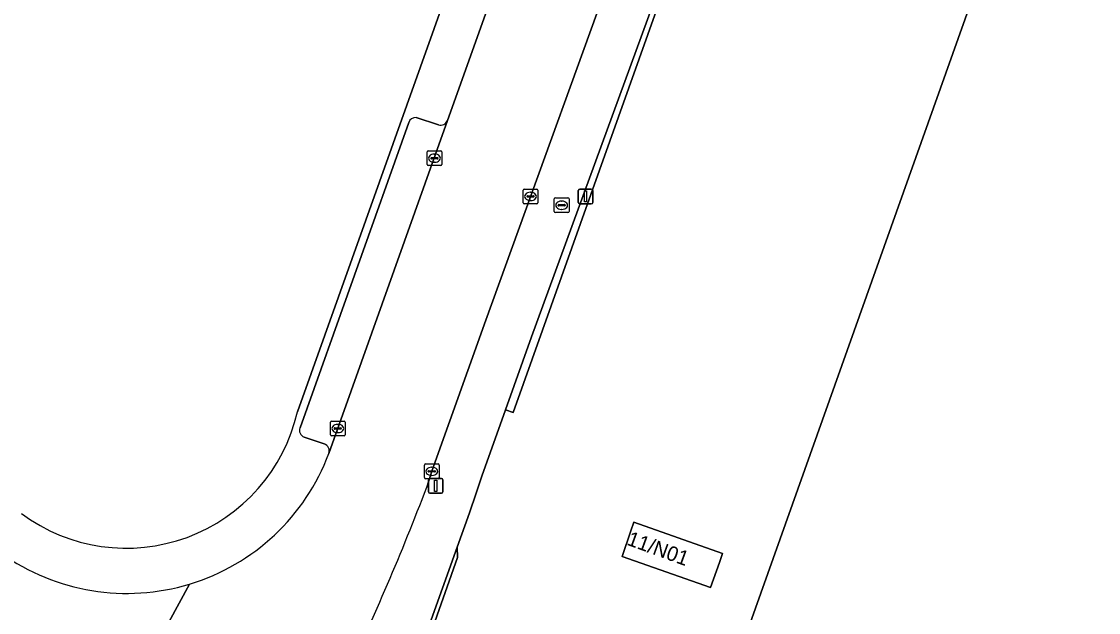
# Model space of a CAD drawing. Extents: x 155018 to 156648, y 383979 to 385733.
# Drawn here: x 155651.5 to 155724.8, y 384875.8 to 384916 of the extents above; entities that cross this region are included whole.
import ezdxf

# ---------------------------------------------------------------- set-up
doc = ezdxf.new("R2010")
doc.units = 0
for name, color, linetype in [('IMGEO_Brandkraan', 7, 'Continuous'), ('IMGEO_Erf', 7, 'Continuous'), ('IMGEO_Groenvoorziening', 7, 'Continuous'), ('IMGEO_Hek', 7, 'Continuous'), ('IMGEO_Kolk', 7, 'Continuous'), ('IMGEO_Lichtmast', 7, 'Continuous'), ('IMGEO_Pand', 7, 'Continuous'), ('IMGEO_Pand_nummerreeks', 7, 'Continuous'), ('IMGEO_Parkeervlak_open', 7, 'Continuous'), ('IMGEO_Rijbaan_lokaal_gesloten', 7, 'Continuous'), ('IMGEO_Voetpad_open', 7, 'Continuous')]:
    doc.layers.add(name, color=color, linetype=linetype)

msp = doc.modelspace()

# ---------------------------------------------------------------- linework, layer by layer
at = {"layer": 'IMGEO_Brandkraan'}
for p, q in [((155687.748, 384903.067), (155687.748, 384903.919)), ((155687.823, 384903.993), (155688.675, 384903.993)), ((155688.007, 384903.487), (155688.007, 384903.499)), ((155688.445, 384903.45), (155688.047, 384903.45)), ((155688.05, 384903.536), (155688.448, 384903.536)), ((155688.236, 384903.773), (155688.261, 384903.773)), ((155688.491, 384903.499), (155688.491, 384903.487)), ((155688.749, 384903.919), (155688.749, 384903.067)), ((155688.675, 384902.993), (155687.823, 384902.993)), ((155688.259, 384903.213), (155688.234, 384903.213))]:
    msp.add_line(p, q, dxfattribs=at)
for points in [[(155687.748, 384903.067), (155687.748, 384903.919)], [(155687.823, 384903.993), (155688.675, 384903.993)], [(155688.749, 384903.919), (155688.749, 384903.067)], [(155688.675, 384902.993), (155687.823, 384902.993)]]:
    msp.add_lwpolyline(points, dxfattribs=at)
for centre, radius, start, end in [((155687.825, 384903.917), 0.0765, 91.55205, 178.44795), ((155687.825, 384903.917), 0.0765, 91.55205, 178.44795), ((155688.047, 384903.496), 0.0403, 85.87752, 175.75265), ((155688.044, 384903.486), 0.0366, 178.93798, 274.71019), ((155688.448, 384903.493), 0.043, 264.86636, 352.45326), ((155688.452, 384903.498), 0.0386, 1.73085, 96.63898), ((155688.673, 384903.917), 0.0765, 1.55205, 88.44795), ((155688.673, 384903.917), 0.0765, 1.55205, 88.44795), ((155687.825, 384903.069), 0.0765, 181.55205, 268.44795), ((155687.825, 384903.069), 0.0765, 181.55205, 268.44795), ((155688.673, 384903.069), 0.0765, 271.55205, 358.44795), ((155688.673, 384903.069), 0.0765, 271.55205, 358.44795)]:
    msp.add_arc(centre, radius, start, end, dxfattribs=at)
for centre, major_axis, ratio, start_param, end_param in [((155688.235, 384903.493), (-0.387, 0.002), 0.722429, 4.712389, 7.853982), ((155688.26, 384903.493), (-0.39, 0.002), 0.717154, 1.570796, 4.712389)]:
    msp.add_ellipse(centre, major_axis=major_axis, ratio=ratio, start_param=start_param, end_param=end_param, dxfattribs=at)
at = {"layer": 'IMGEO_Erf'}
for points in [[(155819.22, 384821.585), (155773.299, 384837.894), (155771.729, 384833.45), (155765.854, 384835.53), (155767.438, 384839.985), (155767.038, 384840.129), (155766.348, 384838.189), (155696.765, 384862.93), (155727.468, 384949.235), (155728.915, 384948.717), (155740.174, 384980.395), (155746.303, 384997.642), (155748.837, 385004.772), (155747.33, 385005.279), (155749.138, 385010.33), (155750.623, 385009.797), (155753.183, 385017.001), (155762.359, 385042.817)], [(155730.975, 385018.536), (155724.402, 385000), (155719.139, 384985.171), (155718.598, 384983.687), (155716.009, 384976.585), (155715.7, 384975.738), (155702.844, 384939.771), (155702.172, 384937.868), (155696.786, 384922.628), (155696.12, 384920.743), (155684.958, 384889.381), (155684.425, 384889.57), (155682.806, 384885.06), (155682.424, 384883.902), (155681.972, 384882.563), (155681.138, 384880.234), (155681.15, 384879.519), (155676.547, 384866.454), (155676.35, 384866.575), (155669.497, 384856.797), (155669.212, 384856.331), (155667.198, 384853.508), (155667.02, 384853.625), (155588.106, 384741.158)], [(155670.262, 384889.44), (155694.342, 384956.978)]]:
    msp.add_lwpolyline(points, dxfattribs=at)
msp.add_lwpolyline([(155698.983, 384879.192), (155698.375, 384877.482), (155692.358, 384879.59), (155692.96, 384881.34), (155693.162, 384881.929), (155699.197, 384879.795)], close=True, dxfattribs=at)
msp.add_arc((155658.606, 384892.113), 11.959, 233.42553, 347.08496, dxfattribs=at)
at = {"layer": 'IMGEO_Groenvoorziening'}
for points in [[(155684.958, 384889.381), (155696.12, 384920.743), (155696.786, 384922.628), (155696.507, 384922.737), (155686.206, 384894.532), (155684.425, 384889.57)], [(155681.15, 384879.519), (155681.138, 384880.234), (155676.369, 384866.915), (155676.09, 384867.098), (155676.052, 384866.993), (155676.35, 384866.575), (155676.547, 384866.454)]]:
    msp.add_lwpolyline(points, close=True, dxfattribs=at)
at = {"layer": 'IMGEO_Hek'}
for points in [[(155696.786, 384922.628), (155696.12, 384920.743), (155684.958, 384889.381)], [(155681.15, 384879.519), (155676.547, 384866.454), (155676.35, 384866.575)]]:
    msp.add_lwpolyline(points, dxfattribs=at)
at = {"layer": 'IMGEO_Kolk'}
for p, q in [((155679.088, 384906.271), (155679.088, 384907.123)), ((155679.163, 384907.197), (155680.015, 384907.197)), ((155679.576, 384906.977), (155679.601, 384906.977)), ((155680.089, 384907.123), (155680.089, 384906.271)), ((155679.347, 384906.691), (155679.347, 384906.703)), ((155679.785, 384906.654), (155679.387, 384906.654)), ((155679.39, 384906.74), (155679.788, 384906.74)), ((155679.599, 384906.417), (155679.574, 384906.417)), ((155679.831, 384906.703), (155679.831, 384906.691)), ((155680.015, 384906.197), (155679.163, 384906.197)), ((155685.628, 384903.668), (155685.628, 384904.52)), ((155685.703, 384904.594), (155686.555, 384904.594)), ((155685.887, 384904.088), (155685.887, 384904.1)), ((155686.325, 384904.051), (155685.927, 384904.051)), ((155685.93, 384904.137), (155686.328, 384904.137)), ((155686.116, 384904.374), (155686.141, 384904.374)), ((155686.371, 384904.1), (155686.371, 384904.088)), ((155686.629, 384904.52), (155686.629, 384903.668)), ((155686.555, 384903.594), (155685.703, 384903.594)), ((155686.139, 384903.814), (155686.114, 384903.814)), ((155672.509, 384887.876), (155672.509, 384888.728)), ((155672.584, 384888.802), (155673.436, 384888.802)), ((155673.51, 384888.728), (155673.51, 384887.876)), ((155672.768, 384888.296), (155672.768, 384888.308)), ((155673.206, 384888.259), (155672.808, 384888.259)), ((155672.811, 384888.345), (155673.209, 384888.345)), ((155673.02, 384888.022), (155672.995, 384888.022)), ((155672.997, 384888.582), (155673.022, 384888.582)), ((155673.252, 384888.308), (155673.252, 384888.296)), ((155673.436, 384887.802), (155672.584, 384887.802)), ((155678.907, 384884.96), (155678.907, 384885.812)), ((155678.982, 384885.886), (155679.834, 384885.886)), ((155679.908, 384885.812), (155679.908, 384884.96)), ((155679.166, 384885.38), (155679.166, 384885.392)), ((155679.604, 384885.343), (155679.206, 384885.343)), ((155679.209, 384885.429), (155679.607, 384885.429)), ((155679.418, 384885.106), (155679.393, 384885.106)), ((155679.395, 384885.666), (155679.42, 384885.666)), ((155679.65, 384885.392), (155679.65, 384885.38)), ((155679.834, 384884.886), (155678.982, 384884.886))]:
    msp.add_line(p, q, dxfattribs=at)
for points in [[(155679.088, 384906.271), (155679.088, 384907.123)], [(155679.163, 384907.197), (155680.015, 384907.197)], [(155680.089, 384907.123), (155680.089, 384906.271)], [(155680.015, 384906.197), (155679.163, 384906.197)], [(155685.628, 384903.668), (155685.628, 384904.52)], [(155685.703, 384904.594), (155686.555, 384904.594)], [(155686.629, 384904.52), (155686.629, 384903.668)], [(155686.555, 384903.594), (155685.703, 384903.594)], [(155672.509, 384887.876), (155672.509, 384888.728)], [(155672.584, 384888.802), (155673.436, 384888.802)], [(155673.51, 384888.728), (155673.51, 384887.876)], [(155673.436, 384887.802), (155672.584, 384887.802)], [(155678.907, 384884.96), (155678.907, 384885.812)], [(155678.982, 384885.886), (155679.834, 384885.886)], [(155679.908, 384885.812), (155679.908, 384884.96)], [(155679.834, 384884.886), (155678.982, 384884.886)]]:
    msp.add_lwpolyline(points, dxfattribs=at)
for centre, radius, start, end in [((155679.165, 384907.121), 0.0765, 91.55205, 178.44795), ((155679.165, 384907.121), 0.0765, 91.55205, 178.44795), ((155680.013, 384907.121), 0.0765, 1.55205, 88.44795), ((155680.013, 384907.121), 0.0765, 1.55205, 88.44795), ((155679.165, 384906.273), 0.0765, 181.55205, 268.44795), ((155679.165, 384906.273), 0.0765, 181.55205, 268.44795), ((155679.387, 384906.7), 0.0403, 85.87752, 175.75265), ((155679.384, 384906.69), 0.0366, 178.93798, 274.71019), ((155679.788, 384906.697), 0.043, 264.86636, 352.45326), ((155679.792, 384906.702), 0.0386, 1.73085, 96.63898), ((155680.013, 384906.273), 0.0765, 271.55205, 358.44795), ((155680.013, 384906.273), 0.0765, 271.55205, 358.44795), ((155685.705, 384904.518), 0.0765, 91.55205, 178.44795), ((155685.705, 384904.518), 0.0765, 91.55205, 178.44795), ((155685.927, 384904.097), 0.0403, 85.87752, 175.75265), ((155685.924, 384904.087), 0.0366, 178.93798, 274.71019), ((155686.328, 384904.094), 0.043, 264.86636, 352.45326), ((155686.332, 384904.099), 0.0386, 1.73085, 96.63898), ((155686.553, 384904.518), 0.0765, 1.55205, 88.44795), ((155686.553, 384904.518), 0.0765, 1.55205, 88.44795), ((155685.705, 384903.67), 0.0765, 181.55205, 268.44795), ((155685.705, 384903.67), 0.0765, 181.55205, 268.44795), ((155686.553, 384903.67), 0.0765, 271.55205, 358.44795), ((155686.553, 384903.67), 0.0765, 271.55205, 358.44795), ((155672.586, 384888.726), 0.0765, 91.55205, 178.44795), ((155672.586, 384888.726), 0.0765, 91.55205, 178.44795), ((155673.434, 384888.726), 0.0765, 1.55205, 88.44795), ((155673.434, 384888.726), 0.0765, 1.55205, 88.44795), ((155672.808, 384888.305), 0.0403, 85.87752, 175.75265), ((155672.805, 384888.295), 0.0366, 178.93798, 274.71019), ((155673.209, 384888.302), 0.043, 264.86636, 352.45326), ((155673.213, 384888.307), 0.0386, 1.73085, 96.63898), ((155672.586, 384887.878), 0.0765, 181.55205, 268.44795), ((155672.586, 384887.878), 0.0765, 181.55205, 268.44795), ((155673.434, 384887.878), 0.0765, 271.55205, 358.44795), ((155673.434, 384887.878), 0.0765, 271.55205, 358.44795), ((155678.984, 384885.81), 0.0765, 91.55205, 178.44795), ((155678.984, 384885.81), 0.0765, 91.55205, 178.44795), ((155679.832, 384885.81), 0.0765, 1.55205, 88.44795), ((155679.832, 384885.81), 0.0765, 1.55205, 88.44795), ((155678.984, 384884.962), 0.0765, 181.55205, 268.44795), ((155678.984, 384884.962), 0.0765, 181.55205, 268.44795), ((155679.206, 384885.389), 0.0403, 85.87752, 175.75265), ((155679.203, 384885.379), 0.0366, 178.93798, 274.71019), ((155679.607, 384885.386), 0.043, 264.86636, 352.45326), ((155679.611, 384885.391), 0.0386, 1.73085, 96.63898), ((155679.832, 384884.962), 0.0765, 271.55205, 358.44795), ((155679.832, 384884.962), 0.0765, 271.55205, 358.44795)]:
    msp.add_arc(centre, radius, start, end, dxfattribs=at)
for centre, major_axis, ratio, start_param, end_param in [((155679.575, 384906.697), (-0.387, 0.002), 0.722429, 4.712389, 7.853982), ((155679.6, 384906.697), (-0.39, 0.002), 0.717154, 1.570796, 4.712389), ((155686.115, 384904.094), (-0.387, 0.002), 0.722429, 4.712389, 7.853982), ((155686.14, 384904.094), (-0.39, 0.002), 0.717154, 1.570796, 4.712389), ((155672.996, 384888.302), (-0.387, 0.002), 0.722429, 4.712389, 7.853982), ((155673.021, 384888.302), (-0.39, 0.002), 0.717154, 1.570796, 4.712389), ((155679.394, 384885.386), (-0.387, 0.002), 0.722429, 4.712389, 7.853982), ((155679.419, 384885.386), (-0.39, 0.002), 0.717154, 1.570796, 4.712389)]:
    msp.add_ellipse(centre, major_axis=major_axis, ratio=ratio, start_param=start_param, end_param=end_param, dxfattribs=at)
at = {"layer": 'IMGEO_Lichtmast'}
for p, q in [((155689.378, 384903.69), (155689.378, 384904.49)), ((155689.378, 384904.49), (155689.378, 384903.69)), ((155689.478, 384904.59), (155690.268, 384904.59)), ((155690.268, 384904.59), (155689.478, 384904.59)), ((155690.368, 384904.49), (155690.368, 384903.69)), ((155690.368, 384903.69), (155690.368, 384904.49)), ((155690.268, 384903.59), (155689.478, 384903.59)), ((155689.478, 384903.59), (155690.268, 384903.59)), ((155679.173, 384883.998), (155679.173, 384884.798)), ((155679.173, 384884.798), (155679.173, 384883.998)), ((155679.273, 384884.898), (155680.063, 384884.898)), ((155680.063, 384884.898), (155679.273, 384884.898)), ((155680.163, 384884.798), (155680.163, 384883.998)), ((155680.163, 384883.998), (155680.163, 384884.798)), ((155680.063, 384883.898), (155679.273, 384883.898)), ((155679.273, 384883.898), (155680.063, 384883.898))]:
    msp.add_line(p, q, dxfattribs=at)
for points in [[(155689.798, 384904.465), (155689.948, 384904.465), (155689.948, 384903.715), (155689.798, 384903.715), (155689.798, 384904.465)], [(155679.593, 384884.773), (155679.743, 384884.773), (155679.743, 384884.023), (155679.593, 384884.023), (155679.593, 384884.773)]]:
    msp.add_lwpolyline(points, dxfattribs=at)
for centre, start, end in [((155689.478, 384904.49), 90, 180), ((155689.478, 384904.49), 90, 180), ((155690.268, 384904.49), 0, 90), ((155690.268, 384904.49), 360, 90), ((155689.478, 384903.69), 180, 270), ((155689.478, 384903.69), 180, 270), ((155690.268, 384903.69), 270, 0), ((155690.268, 384903.69), 270, 0), ((155679.273, 384884.798), 90, 180), ((155679.273, 384884.798), 90, 180), ((155680.063, 384884.798), 0, 90), ((155680.063, 384884.798), 360, 90), ((155679.273, 384883.998), 180, 270), ((155679.273, 384883.998), 180, 270), ((155680.063, 384883.998), 270, 0), ((155680.063, 384883.998), 270, 0)]:
    msp.add_arc(centre, 0.1, start, end, dxfattribs=at)
at = {"layer": 'IMGEO_Pand'}
msp.add_lwpolyline([(155828.255, 384911.336), (155796.179, 384922.734), (155808.139, 384956.274), (155787.494, 384963.57), (155797.027, 384990.446), (155809.649, 385026.028), (155762.359, 385042.817), (155753.183, 385017.001), (155750.623, 385009.797), (155749.138, 385010.33), (155747.33, 385005.279), (155748.837, 385004.772), (155746.303, 384997.642), (155740.174, 384980.395), (155728.915, 384948.717), (155727.468, 384949.235), (155696.765, 384862.93), (155766.348, 384838.189), (155767.038, 384840.129), (155767.438, 384839.985), (155765.854, 384835.53), (155771.729, 384833.45), (155773.299, 384837.894), (155819.22, 384821.585)], dxfattribs=at)
msp.add_lwpolyline([(155698.983, 384879.192), (155699.197, 384879.795), (155693.162, 384881.929), (155692.96, 384881.34), (155692.358, 384879.59), (155698.375, 384877.482)], close=True, dxfattribs=at)
at = {"layer": 'IMGEO_Parkeervlak_open'}
for points in [[(155672.406, 384886.601), (155680.471, 384909.27)], [(155679.86, 384908.959), (155678.342, 384909.455)], [(155677.837, 384909.136), (155670.437, 384888.352)], [(155670.727, 384887.719), (155672.089, 384887.255)]]:
    msp.add_lwpolyline(points, dxfattribs=at)
for centre, radius, start, end in [((155678.292, 384908.975), 0.482, 84.0123, 160.54753), ((155679.997, 384909.446), 0.506, 254.29188, 339.66045), ((155670.876, 384888.17), 0.475, 157.46603, 251.7624), ((155671.903, 384886.761), 0.528, 342.37794, 69.34187)]:
    msp.add_arc(centre, radius, start, end, dxfattribs=at)
at = {"layer": 'IMGEO_Rijbaan_lokaal_gesloten'}
for points in [[(155764.837, 385117.429), (155755.507, 385119.738), (155752.407, 385110.986), (155749.126, 385101.756), (155741.863, 385081.49), (155734.635, 385061.204), (155727.42, 385041.095), (155724.606, 385033.163), (155719.998, 385020.177), (155712.839, 385000), (155711.66, 384996.694), (155697.277, 384956.434), (155683.176, 384916.819), (155680.471, 384909.27), (155672.406, 384886.601)], [(155679.062, 384884.306), (155679.409, 384885.386), (155683.078, 384895.663), (155693.322, 384923.959), (155698.719, 384939.029), (155712.551, 384977.822), (155712.738, 384978.347), (155715.089, 384984.941), (155720.459, 385000), (155723.632, 385008.98), (155724.976, 385012.761), (155727.017, 385018.428), (155728.003, 385021.255), (155731.055, 385029.838), (155733.848, 385037.615), (155741.439, 385058.768), (155756.537, 385101.063), (155759.644, 385109.754)], [(155654.873, 384862.94), (155662.924, 384877.712)], [(155662.924, 384877.712), (155654.873, 384862.94)]]:
    msp.add_lwpolyline(points, dxfattribs=at)
for centre, radius, start, end in [((155658.646, 384891.777), 14.701, 286.9163, 339.38607), ((155522.654, 384943.7), 167.306, 334.32678, 339.20632), ((155658.649, 384891.78), 14.703, 234.44429, 286.90502)]:
    msp.add_arc(centre, radius, start, end, dxfattribs=at)
at = {"layer": 'IMGEO_Voetpad_open'}
for points in [[(155695.309, 384956.629), (155695.291, 384956.637), (155694.342, 384956.978), (155670.262, 384889.44)], [(155673.443, 384871.217), (155676.052, 384866.993), (155676.09, 384867.098), (155676.369, 384866.915), (155681.138, 384880.234), (155681.972, 384882.563), (155682.424, 384883.902), (155682.806, 384885.06), (155684.425, 384889.57), (155686.206, 384894.532), (155696.507, 384922.737), (155693.322, 384923.959), (155683.078, 384895.663), (155679.409, 384885.386), (155679.062, 384884.306)], [(155680.471, 384909.27), (155683.176, 384916.819)], [(155678.342, 384909.455), (155679.86, 384908.959)], [(155670.437, 384888.352), (155677.837, 384909.136)], [(155672.089, 384887.255), (155670.727, 384887.719)]]:
    msp.add_lwpolyline(points, dxfattribs=at)
for centre, radius, start, end in [((155678.292, 384908.975), 0.482, 84.0123, 160.54753), ((155679.997, 384909.446), 0.506, 254.29188, 339.66045), ((155658.606, 384892.113), 11.959, 233.42553, 347.08496), ((155670.876, 384888.17), 0.475, 157.46603, 251.7624), ((155671.903, 384886.761), 0.528, 342.37794, 69.34187), ((155658.646, 384891.777), 14.701, 286.9163, 339.38607), ((155522.654, 384943.7), 167.306, 334.32678, 339.20632), ((155658.649, 384891.78), 14.703, 234.44429, 286.90502)]:
    msp.add_arc(centre, radius, start, end, dxfattribs=at)

# ---------------------------------------------------------------- texts
at = {"layer": 'IMGEO_Pand_nummerreeks'}
msp.add_text('11/N01', height=1, rotation=340.01689, dxfattribs=at).set_placement((155692.626, 384880.402))

doc.saveas('drawing.dxf')
